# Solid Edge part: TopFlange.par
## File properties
Author: ptcarter
Template: ANSIMM.PAR
Last saved by: ptcarter
Revision: 40
Application: Solid Edge
Accuracy: 0.99
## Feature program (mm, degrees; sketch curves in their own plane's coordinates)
sketch for "unnamed Protrusion 1" plane through (0, 0, 0) normal (0, 0, 1) x-axis (1, 0, 0)
  line (-20, 30) -> (20, 30)
  arc centre (20, 20) radius 10 from (20, 30) to (30, 20) cw
  line (30, 20) -> (30, -20)
  arc centre (20, -20) radius 10 from (30, -20) to (20, -30) cw
  line (20, -30) -> (-20, -30)
  arc centre (-20, -20) radius 10 from (-20, -30) to (-30, -20) cw
  line (-30, 20) -> (-30, -20)
  arc centre (-20, 20) radius 10 from (-30, 20) to (-20, 30) cw
  dimension (linear) = 20
extrude "unnamed Protrusion 1" add finite 10 along +normal
fillet "unnamed Round 1"
sketch for "Hole_1" plane through (0, 0, 10) normal (0, 0, 1) x-axis (1, 0, 0)
  hole centre (-20, 20) bore radius 5
hole "Hole_1" through
sketch for "unnamed Hole 1" plane through (0, 0, 10) normal (0, 0, 1) x-axis (1, 0, 0)
  hole centre (20, 20) bore radius 5
hole "unnamed Hole 1" through
sketch for "unnamed Hole 2" plane through (0, 0, 10) normal (0, 0, 1) x-axis (1, 0, 0)
  hole centre (20, -20) bore radius 5
hole "unnamed Hole 2" through
sketch for "unnamed Hole 3" plane through (0, 0, 10) normal (0, 0, 1) x-axis (1, 0, 0)
  hole centre (-20, -20) bore radius 5
hole "unnamed Hole 3" through
pattern "unnamed Pattern 1" of "Hole_1", "unnamed Hole 1", "unnamed Hole 2", "unnamed Hole 3"
sketch for "unnamed Cutout 1" plane through (0, 0, 10) normal (0, 0, 1) x-axis (1, 0, 0)
  line (26.7175, 13.2825) -> (30, 16.565)
  arc centre (20, 20) radius 9.5 from (26.7175, 13.2825) to (13.2825, 26.7175) cw
  line (13.2825, 26.7175) -> (16.565, 30)
extrude "unnamed Cutout 1" cut finite 3 along -normal
mirror "unnamed Mirror 1" of "unnamed Cutout 1" about plane through (0, 0, 0) normal (0, -1, 0)
extrude "unnamed Cutout 2" cut finite 3
mirror "unnamed Mirror 2" of "unnamed Mirror 1" about plane through (0, 0, 0) normal (1, 0, 0)
extrude "unnamed Cutout 3" cut finite 3
mirror "unnamed Mirror 3" of "unnamed Mirror 2" about plane through (0, 0, 0) normal (0, -1, 0)
extrude "unnamed Cutout 4" cut finite 3
sketch for "Hole_5" plane through (0, 0, 10) normal (0, 0, 1) x-axis (1, 0, 0)
  hole centre (0, 0) bore radius 7.5
hole "Hole_5" through
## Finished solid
Body 1: solid body, 35 faces, 94 edges, 56 vertices.
  Faces by surface: plane 18, cylinder 17
  Edges by curve: line 60, circle 26, ellipse 8
Bounding box of the edges (mm): 60.000 x 60.000 x 10.000, from (-30, -30, 0) to (30, 30, 10).
Cylindrical faces by radius (mm): R2 x4, R5 x4, R7.5 x1, R9.5 x4, R10 x4
Planar faces by outward normal: +x 1, +y 1, +z 5, -x 1, -y 1, -z 1, oblique 8
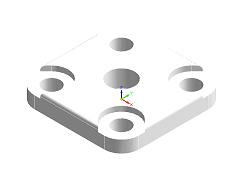
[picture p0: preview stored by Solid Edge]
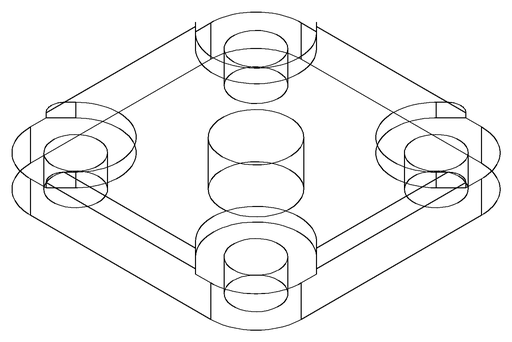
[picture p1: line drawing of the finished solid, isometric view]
